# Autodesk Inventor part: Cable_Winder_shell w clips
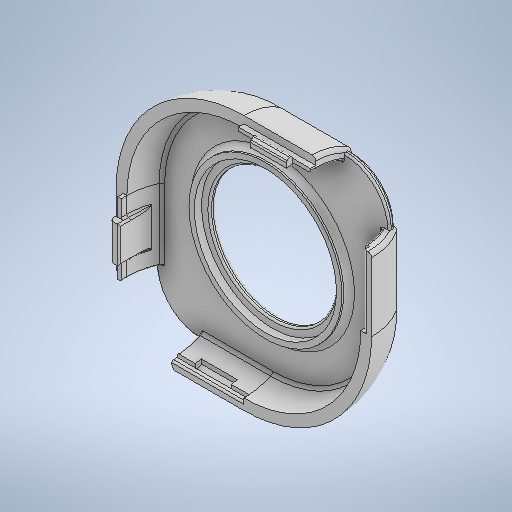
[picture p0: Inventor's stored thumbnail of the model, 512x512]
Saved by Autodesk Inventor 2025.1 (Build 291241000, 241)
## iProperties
Created: 2025-11
Part Number: Cable_Winder_shell w clips
Material: Generico
Document SubType Name: Modeling
Designer: ut03
Density: 1 g/cm^3
Appearance: Default
Author: ut03
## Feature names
1. Estrusione1 [Extrusion]
2. Estrusione2 [Extrusion]
3. Estrusione5 [Extrusion]
4. Raccordo6 [Fillet]
5. Sweep3
6. Sweep4
7. Estrusione8 [Extrusion]
8. Estrusione9 [Extrusion]
9. Raccordo9 [Fillet]
10. Raccordo10 [Fillet]
11. Smusso1 [Chamfer]
12. Smusso2 [Chamfer]
13. Estrusione10 [Extrusion]
14. Estrusione11 [Extrusion]
15. Estrusione12 [Extrusion]
16. Smusso3 [Chamfer]
17. Estrusione13 [Extrusion]
18. Smusso4 [Chamfer]
19. Estrusione14 [Extrusion]
20. Estrusione15 [Extrusion]
21. Estrusione16 [Extrusion]
22. Estrusione17 [Extrusion]
23. Raccordo11 [Fillet]
## Parameters: d0 = 65 mm, d1 = 65 mm, d2 = 35 mm, d3 = 2 mm, d4 = 0, d5 = 39.5 mm, d6 = 1.5 mm, d7 = 2 mm, d8 = 0, d9 = 2 mm, d23 = 0, d30 = 1.5 mm, d51 = -12.5 mm, d52 = -12.5 mm, d53 = 8 mm, d54 = 3 mm, d55 = 8 mm, d56 = 3 mm, d57 = 8 mm, d58 = 1.5 mm, d59 = 1.5 mm, d60 = 0, d61 = 0, d62 = 0, d63 = 0, d64 = 1 mm, d66 = 1 mm, d67 = 1.5 mm, d68 = 0, d70 = 3 mm, d71 = 3 mm, d73 = 1.5 mm, d74 = 0, d75 = 1 mm, d76 = 0.5 mm, d77 = 1 mm, d78 = 2 mm, d79 = 45 deg, d80 = 1 mm, d81 = 2 mm, d82 = 45 deg, d83 = -2 mm, d84 = 5 mm, d85 = 1 mm, d86 = 2.5 mm, d89 = 1 mm, d90 = 5 mm, d91 = 0, d92 = -2 mm, d99 = 3 mm, d100 = 5 mm, d101 = 0, d102 = -2 mm, d103 = 5 mm, d104 = 2.024 mm, d105 = 2.5 mm, d106 = 1 mm, d108 = 2.02419 mm, d109 = 4.024 mm, d110 = 0.25 mm, d111 = 5.25 mm, d112 = 0, d113 = 0, d114 = 0.5 mm, d115 = 2 mm, d116 = 45 deg, d117 = -2 mm, d118 = 5 mm, d125 = 0.25 mm, d126 = 5 mm, d127 = 0, d128 = 0, d129 = 0.25 mm, d130 = 0.25 mm, d131 = 1.25 mm, d132 = 1.25 mm, d133 = 1.25 mm, d134 = 1 mm, d135 = 0.25 mm, d136 = 0.25 mm, d137 = 1 mm, d138 = 0.5 mm, d139 = 1 mm, d140 = 0.5 mm, d141 = 0.5 mm, d142 = 2 mm, d143 = 45 deg, d144 = -5 mm, d146 = 2 mm, d147 = 60 deg, d148 = 0.5 mm, d150 = 0, d151 = -5 mm, d156 = 0, d157 = -5 mm, d159 = 0, d160 = -5 mm, d162 = 0, d163 = 0.5 mm
